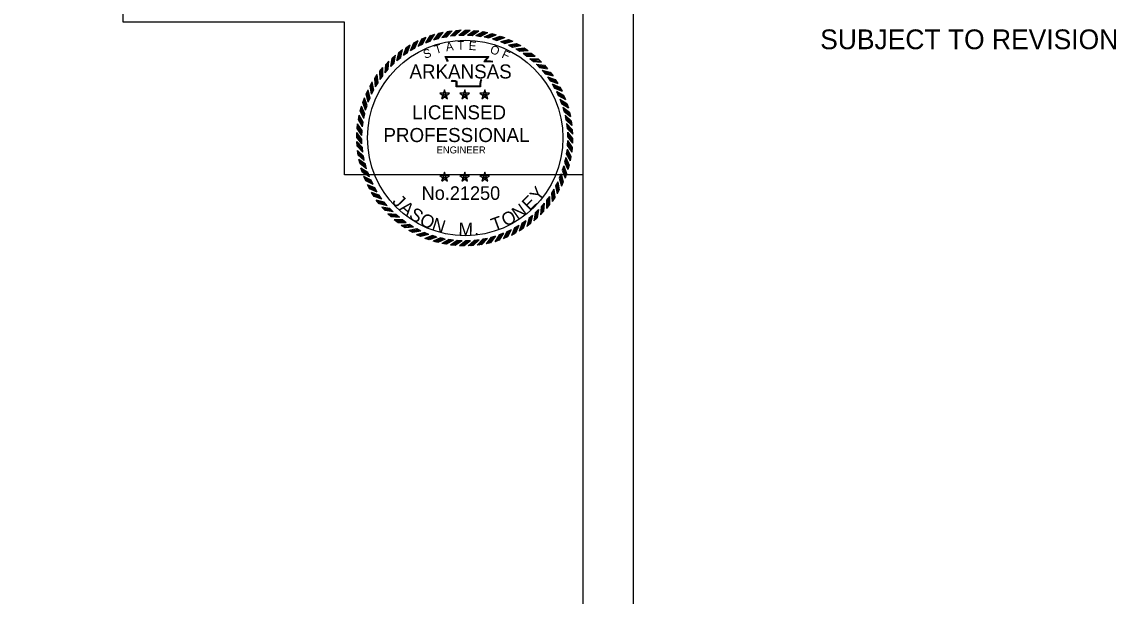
# Model space of a CAD drawing. Extents: x 0 to 1228740, y 0 to 152440.
# Drawn here: x 26.96 to 39.56, y 12.84 to 19.44 of the extents above; entities that cross this region are included whole.
import ezdxf

# ---------------------------------------------------------------- set-up
doc = ezdxf.new("R2010")
doc.units = 0
for name, color, linetype in [('G-ANNO-NPLT', 7, 'Continuous'), ('R_Border', 7, 'Continuous'), ('R_Draft', 7, 'Continuous'), ('R_No Plot', 7, 'Continuous'), ('STAMP', 7, 'Continuous')]:
    doc.layers.add(name, color=color, linetype=linetype)

msp = doc.modelspace()

# ---------------------------------------------------------------- linework, layer by layer
at = {"layer": 'G-ANNO-NPLT'}
msp.add_circle((32.064, 18.109), 1.124, dxfattribs=at)
at = {"layer": 'R_Border'}
msp.add_line((33.423, 0.577), (33.423, 21.423), dxfattribs=at)
msp.add_lwpolyline([(34, 22), (0, 22), (0, 0), (34, 0)], close=True, dxfattribs=at)
at = {"layer": 'R_No Plot'}
for points in [[(27.159, 21.423), (1.516, 21.423), (1.516, 0.577), (33.423, 0.577), (33.423, 17.685), (30.673, 17.685), (30.673, 19.442), (28.127, 19.442), (28.127, 20.435), (27.159, 20.435)], [(27.159, 21.423), (1.516, 21.423), (1.516, 10.871), (33.423, 10.871), (33.423, 17.685), (30.673, 17.685), (30.673, 19.442), (28.127, 19.442), (28.127, 20.435), (27.159, 20.435)]]:
    msp.add_lwpolyline(points, close=True, dxfattribs=at)
at = {"layer": 'STAMP'}
for p, q in [((31.566, 19.248), (31.615, 19.27)), ((31.661, 19.285), (31.713, 19.303)), ((31.76, 19.313), (31.812, 19.327)), ((31.797, 19.264), (31.851, 19.273)), ((31.86, 19.334), (31.914, 19.343)), ((31.894, 19.282), (31.948, 19.287)), ((31.962, 19.346), (32.016, 19.351)), ((31.991, 19.291), (32.045, 19.291)), ((32.065, 19.349), (32.12, 19.349)), ((32.089, 19.293), (32.143, 19.289)), ((32.167, 19.345), (32.221, 19.341)), ((32.186, 19.286), (32.24, 19.278)), ((32.269, 19.332), (32.323, 19.323)), ((32.283, 19.272), (32.336, 19.259)), ((32.369, 19.31), (32.422, 19.297)), ((32.467, 19.28), (32.519, 19.263)), ((31.385, 19.151), (31.43, 19.181)), ((31.473, 19.203), (31.521, 19.23)), ((31.522, 19.165), (31.571, 19.187)), ((31.611, 19.205), (31.662, 19.223)), ((31.703, 19.238), (31.755, 19.252)), ((32.378, 19.249), (32.43, 19.232)), ((32.472, 19.219), (32.522, 19.197)), ((32.562, 19.181), (32.61, 19.155)), ((32.563, 19.243), (32.613, 19.221)), ((32.654, 19.197), (32.703, 19.172)), ((32.742, 19.144), (32.788, 19.115)), ((31.223, 19.026), (31.262, 19.063)), ((31.279, 19), (31.322, 19.034)), ((31.301, 19.092), (31.344, 19.126)), ((31.355, 19.062), (31.401, 19.092)), ((31.436, 19.117), (31.484, 19.143)), ((32.649, 19.135), (32.694, 19.106)), ((32.731, 19.083), (32.775, 19.05)), ((32.809, 19.024), (32.85, 18.988)), ((32.825, 19.084), (32.869, 19.051)), ((32.903, 19.018), (32.944, 18.981)), ((31.083, 18.876), (31.116, 18.919)), ((31.143, 18.86), (31.179, 18.9)), ((31.15, 18.954), (31.186, 18.994)), ((31.208, 18.933), (31.248, 18.97)), ((32.883, 18.959), (32.92, 18.919)), ((32.976, 18.945), (33.013, 18.905)), ((31.023, 18.793), (31.052, 18.839)), ((31.084, 18.782), (31.117, 18.825)), ((32.95, 18.888), (32.984, 18.845)), ((33.011, 18.812), (33.041, 18.767)), ((33.041, 18.866), (33.075, 18.823)), ((33.101, 18.782), (33.131, 18.737)), ((30.924, 18.613), (30.946, 18.663)), ((30.97, 18.705), (30.995, 18.753)), ((30.986, 18.612), (31.012, 18.661)), ((31.032, 18.699), (31.061, 18.745)), ((31.827, 18.663), (31.793, 18.558)), ((31.861, 18.558), (31.827, 18.663)), ((32.058, 18.663), (32.024, 18.558)), ((32.092, 18.558), (32.058, 18.663)), ((32.289, 18.663), (32.255, 18.558)), ((32.323, 18.558), (32.289, 18.663)), ((33.066, 18.731), (33.092, 18.683)), ((33.114, 18.645), (33.136, 18.596)), ((33.153, 18.694), (33.179, 18.646)), ((30.887, 18.518), (30.904, 18.569)), ((30.949, 18.522), (30.97, 18.572)), ((31.882, 18.623), (31.772, 18.623)), ((31.773, 18.623), (31.861, 18.558)), ((31.794, 18.558), (31.882, 18.623)), ((31.82, 18.605), (31.836, 18.605)), ((31.828, 18.611), (31.828, 18.597)), ((32.113, 18.623), (32.003, 18.623)), ((32.003, 18.623), (32.092, 18.558)), ((32.024, 18.558), (32.113, 18.623)), ((32.05, 18.605), (32.067, 18.605)), ((32.058, 18.611), (32.058, 18.597)), ((32.344, 18.623), (32.234, 18.623)), ((32.234, 18.623), (32.323, 18.558)), ((32.255, 18.558), (32.344, 18.623)), ((32.281, 18.605), (32.297, 18.605)), ((32.289, 18.611), (32.289, 18.597)), ((33.155, 18.556), (33.173, 18.505)), ((33.197, 18.602), (33.22, 18.552)), ((30.857, 18.42), (30.87, 18.472)), ((30.918, 18.429), (30.935, 18.481)), ((33.188, 18.464), (33.202, 18.412)), ((33.234, 18.506), (33.252, 18.454)), ((33.263, 18.407), (33.277, 18.355)), ((30.822, 18.218), (30.826, 18.272)), ((30.835, 18.319), (30.844, 18.373)), ((30.881, 18.237), (30.89, 18.291)), ((30.896, 18.334), (30.909, 18.387)), ((33.213, 18.37), (33.223, 18.316)), ((33.231, 18.274), (33.236, 18.219)), ((33.283, 18.307), (33.293, 18.253)), ((30.817, 18.115), (30.817, 18.17)), ((30.874, 18.139), (30.878, 18.194)), ((33.241, 18.176), (33.241, 18.122)), ((33.295, 18.205), (33.3, 18.151)), ((30.821, 18.013), (30.816, 18.067)), ((30.876, 18.041), (30.876, 18.096)), ((33.242, 18.078), (33.238, 18.024)), ((33.299, 18.103), (33.3, 18.048)), ((30.833, 17.911), (30.824, 17.964)), ((30.886, 17.944), (30.881, 17.998)), ((30.903, 17.848), (30.894, 17.902)), ((33.236, 17.981), (33.227, 17.927)), ((33.281, 17.898), (33.273, 17.845)), ((33.294, 18), (33.29, 17.946)), ((30.854, 17.81), (30.84, 17.863)), ((30.883, 17.712), (30.864, 17.763)), ((30.929, 17.753), (30.915, 17.806)), ((33.198, 17.789), (33.181, 17.737)), ((33.221, 17.884), (33.208, 17.831)), ((33.26, 17.798), (33.247, 17.745)), ((30.919, 17.616), (30.897, 17.666)), ((30.962, 17.661), (30.944, 17.713)), ((31.882, 17.676), (31.772, 17.677)), ((31.773, 17.676), (31.861, 17.612)), ((31.827, 17.716), (31.793, 17.612)), ((31.794, 17.612), (31.882, 17.676)), ((31.82, 17.659), (31.836, 17.659)), ((31.861, 17.612), (31.827, 17.716)), ((31.828, 17.665), (31.828, 17.651)), ((32.113, 17.676), (32.003, 17.677)), ((32.003, 17.676), (32.092, 17.612)), ((32.058, 17.716), (32.024, 17.612)), ((32.024, 17.612), (32.113, 17.676)), ((32.05, 17.659), (32.067, 17.659)), ((32.092, 17.612), (32.058, 17.716)), ((32.058, 17.665), (32.058, 17.651)), ((32.344, 17.676), (32.234, 17.677)), ((32.234, 17.676), (32.323, 17.612)), ((32.289, 17.716), (32.255, 17.612)), ((32.255, 17.612), (32.344, 17.676)), ((32.281, 17.659), (32.297, 17.659)), ((32.323, 17.612), (32.289, 17.716)), ((32.289, 17.665), (32.289, 17.651)), ((33.168, 17.696), (33.147, 17.646)), ((33.23, 17.7), (33.213, 17.648)), ((30.964, 17.524), (30.938, 17.571)), ((31.003, 17.572), (30.98, 17.622)), ((31.051, 17.487), (31.024, 17.535)), ((33.085, 17.519), (33.056, 17.473)), ((33.13, 17.605), (33.105, 17.557)), ((33.147, 17.513), (33.121, 17.465)), ((33.192, 17.605), (33.171, 17.555)), ((31.016, 17.435), (30.986, 17.481)), ((31.075, 17.352), (31.041, 17.394)), ((31.105, 17.406), (31.075, 17.451)), ((33.033, 17.436), (33, 17.393)), ((33.094, 17.425), (33.064, 17.379)), ((31.141, 17.273), (31.104, 17.313)), ((31.167, 17.33), (31.133, 17.372)), ((31.234, 17.259), (31.197, 17.298)), ((32.909, 17.285), (32.869, 17.247)), ((32.967, 17.264), (32.93, 17.223)), ((32.974, 17.358), (32.937, 17.317)), ((33.034, 17.342), (33.001, 17.298)), ((31.213, 17.2), (31.173, 17.237)), ((31.291, 17.134), (31.248, 17.167)), ((31.307, 17.193), (31.267, 17.23)), ((31.385, 17.134), (31.342, 17.168)), ((32.761, 17.156), (32.716, 17.126)), ((32.838, 17.217), (32.795, 17.183)), ((32.894, 17.192), (32.854, 17.154)), ((31.374, 17.074), (31.328, 17.103)), ((31.462, 17.021), (31.414, 17.046)), ((31.468, 17.082), (31.422, 17.112)), ((31.555, 17.037), (31.507, 17.063)), ((31.645, 16.999), (31.595, 17.021)), ((32.506, 17.013), (32.455, 16.994)), ((32.595, 17.053), (32.545, 17.031)), ((32.643, 17.015), (32.596, 16.988)), ((32.68, 17.101), (32.633, 17.075)), ((32.732, 17.067), (32.686, 17.036)), ((32.815, 17.126), (32.773, 17.092)), ((31.554, 16.975), (31.504, 16.996)), ((31.649, 16.937), (31.598, 16.954)), ((31.738, 16.969), (31.686, 16.986)), ((31.748, 16.908), (31.695, 16.92)), ((31.833, 16.946), (31.78, 16.959)), ((31.848, 16.886), (31.794, 16.894)), ((31.93, 16.932), (31.876, 16.94)), ((31.95, 16.873), (31.895, 16.877)), ((32.028, 16.925), (31.973, 16.929)), ((32.126, 16.927), (32.071, 16.926)), ((32.223, 16.936), (32.169, 16.931)), ((32.256, 16.884), (32.203, 16.874)), ((32.319, 16.954), (32.266, 16.944)), ((32.357, 16.904), (32.304, 16.891)), ((32.414, 16.979), (32.361, 16.965)), ((32.455, 16.933), (32.404, 16.915)), ((32.551, 16.97), (32.501, 16.948)), ((32.052, 16.868), (31.998, 16.867)), ((32.154, 16.872), (32.1, 16.867))]:
    msp.add_line(p, q, dxfattribs=at)
for points in [[(31.571, 19.187), (31.615, 19.27)], [(31.611, 19.205), (31.661, 19.284)], [(31.627, 19.211), (31.678, 19.29)], [(31.645, 19.218), (31.696, 19.297)], [(31.662, 19.223), (31.713, 19.303)], [(31.703, 19.238), (31.76, 19.313)], [(31.72, 19.243), (31.777, 19.318)], [(31.738, 19.248), (31.795, 19.323)], [(31.755, 19.252), (31.812, 19.327)], [(31.797, 19.264), (31.86, 19.334)], [(31.814, 19.267), (31.878, 19.337)], [(31.833, 19.27), (31.896, 19.34)], [(31.851, 19.273), (31.914, 19.343)], [(31.893, 19.281), (31.962, 19.346)], [(31.911, 19.283), (31.98, 19.347)], [(31.93, 19.285), (31.998, 19.35)], [(31.948, 19.287), (32.016, 19.351)], [(31.991, 19.291), (32.065, 19.349)], [(32.008, 19.291), (32.083, 19.349)], [(32.027, 19.291), (32.102, 19.349)], [(32.045, 19.291), (32.12, 19.349)], [(32.089, 19.293), (32.167, 19.345)], [(32.106, 19.291), (32.184, 19.343)], [(32.125, 19.29), (32.203, 19.343)], [(32.143, 19.289), (32.221, 19.341)], [(32.186, 19.286), (32.269, 19.332)], [(32.204, 19.283), (32.286, 19.329)], [(32.222, 19.281), (32.305, 19.326)], [(32.24, 19.278), (32.323, 19.323)], [(32.283, 19.271), (32.369, 19.31)], [(32.3, 19.267), (32.386, 19.306)], [(32.319, 19.263), (32.404, 19.302)], [(32.336, 19.259), (32.422, 19.297)], [(32.378, 19.249), (32.467, 19.28)], [(32.395, 19.243), (32.484, 19.275)], [(31.355, 19.062), (31.385, 19.151)], [(31.37, 19.071), (31.4, 19.161)], [(31.385, 19.082), (31.415, 19.171)], [(31.401, 19.092), (31.43, 19.181)], [(31.436, 19.117), (31.473, 19.203)], [(31.452, 19.125), (31.489, 19.211)], [(31.468, 19.134), (31.505, 19.221)], [(31.484, 19.143), (31.521, 19.23)], [(31.522, 19.164), (31.566, 19.248)], [(31.538, 19.171), (31.582, 19.255)], [(31.555, 19.18), (31.599, 19.263)], [(32.413, 19.238), (32.502, 19.269)], [(32.43, 19.232), (32.519, 19.263)], [(32.471, 19.219), (32.562, 19.243)], [(32.487, 19.212), (32.579, 19.236)], [(32.505, 19.205), (32.596, 19.229)], [(32.522, 19.197), (32.613, 19.221)], [(32.562, 19.181), (32.654, 19.197)], [(32.577, 19.172), (32.67, 19.189)], [(32.594, 19.164), (32.687, 19.18)], [(32.61, 19.155), (32.703, 19.172)], [(32.648, 19.135), (32.742, 19.144)], [(31.208, 18.933), (31.223, 19.026)], [(31.221, 18.945), (31.235, 19.038)], [(31.234, 18.958), (31.249, 19.051)], [(31.248, 18.97), (31.262, 19.063)], [(31.279, 19), (31.301, 19.092)], [(31.293, 19.011), (31.315, 19.103)], [(31.307, 19.023), (31.329, 19.115)], [(31.322, 19.034), (31.344, 19.126)], [(31.862, 18.985), (31.833, 19.048), (32.335, 19.048), (32.293, 18.995), (32.327, 18.996), (32.356, 18.996), (32.384, 18.993)], [(31.87, 18.988), (31.846, 19.04), (32.319, 19.04), (32.277, 18.987), (32.328, 18.988), (32.356, 18.988), (32.383, 18.985)], [(32.663, 19.126), (32.757, 19.135)], [(32.679, 19.116), (32.773, 19.125)], [(32.694, 19.106), (32.788, 19.115)], [(32.731, 19.083), (32.825, 19.084)], [(32.745, 19.072), (32.839, 19.073)], [(32.76, 19.061), (32.854, 19.062)], [(32.775, 19.05), (32.869, 19.051)], [(32.809, 19.024), (32.903, 19.018)], [(31.106, 18.811), (31.105, 18.905)], [(31.117, 18.825), (31.116, 18.919)], [(31.143, 18.86), (31.15, 18.954)], [(31.155, 18.873), (31.162, 18.967)], [(31.167, 18.887), (31.174, 18.981)], [(31.179, 18.9), (31.186, 18.994)], [(32.822, 19.012), (32.916, 19.006)], [(32.837, 19), (32.93, 18.993)], [(32.85, 18.988), (32.944, 18.981)], [(32.882, 18.959), (32.975, 18.945)], [(32.894, 18.946), (32.987, 18.932)], [(32.908, 18.933), (33.001, 18.918)], [(32.92, 18.919), (33.013, 18.905)], [(31.032, 18.699), (31.023, 18.793)], [(31.041, 18.714), (31.033, 18.807)], [(31.051, 18.73), (31.042, 18.824)], [(31.061, 18.745), (31.052, 18.839)], [(31.084, 18.782), (31.083, 18.876)], [(31.095, 18.796), (31.094, 18.89)], [(32.256, 18.775), (32.248, 18.768), (32.245, 18.757), (32.242, 18.731), (32.242, 18.697), (31.962, 18.697), (31.962, 18.743), (31.962, 18.754), (31.95, 18.757), (31.911, 18.757), (31.904, 18.768)], [(32.251, 18.781), (32.241, 18.772), (32.237, 18.759), (32.234, 18.732), (32.234, 18.705), (31.97, 18.705), (31.97, 18.743), (31.97, 18.76), (31.952, 18.765), (31.915, 18.765), (31.91, 18.772)], [(32.95, 18.888), (33.041, 18.866)], [(32.961, 18.874), (33.052, 18.852)], [(32.973, 18.86), (33.064, 18.838)], [(32.984, 18.846), (33.075, 18.823)], [(33.011, 18.812), (33.101, 18.782)], [(33.021, 18.797), (33.11, 18.768)], [(33.032, 18.782), (33.121, 18.752)], [(33.041, 18.767), (33.131, 18.737)], [(30.963, 18.556), (30.939, 18.647)], [(30.97, 18.572), (30.946, 18.663)], [(30.986, 18.612), (30.97, 18.705)], [(30.995, 18.628), (30.978, 18.72)], [(31.003, 18.645), (30.987, 18.737)], [(31.012, 18.66), (30.995, 18.753)], [(33.066, 18.731), (33.153, 18.694)], [(33.074, 18.715), (33.161, 18.679)], [(33.084, 18.699), (33.17, 18.662)], [(33.092, 18.683), (33.179, 18.646)], [(33.114, 18.646), (33.197, 18.602)], [(30.918, 18.429), (30.887, 18.518)], [(30.924, 18.446), (30.892, 18.534)], [(30.929, 18.464), (30.898, 18.552)], [(30.935, 18.481), (30.904, 18.569)], [(30.949, 18.522), (30.925, 18.613)], [(30.956, 18.538), (30.932, 18.629)], [(33.121, 18.629), (33.204, 18.586)], [(33.129, 18.612), (33.212, 18.568)], [(33.136, 18.596), (33.22, 18.552)], [(33.155, 18.557), (33.234, 18.506)], [(33.16, 18.54), (33.24, 18.489)], [(33.167, 18.522), (33.246, 18.472)], [(30.896, 18.334), (30.857, 18.42)], [(30.9, 18.351), (30.861, 18.437)], [(30.904, 18.369), (30.865, 18.455)], [(30.908, 18.387), (30.87, 18.473)], [(33.173, 18.505), (33.252, 18.454)], [(33.188, 18.464), (33.263, 18.407)], [(33.192, 18.447), (33.267, 18.39)], [(33.197, 18.429), (33.272, 18.372)], [(33.202, 18.412), (33.277, 18.355)], [(30.878, 18.194), (30.826, 18.272)], [(30.881, 18.237), (30.835, 18.319)], [(30.884, 18.254), (30.838, 18.337)], [(30.886, 18.273), (30.841, 18.355)], [(30.889, 18.291), (30.844, 18.373)], [(33.213, 18.37), (33.283, 18.307)], [(33.216, 18.353), (33.286, 18.29)], [(33.22, 18.334), (33.29, 18.271)], [(33.223, 18.316), (33.293, 18.253)], [(33.231, 18.274), (33.295, 18.205)], [(30.875, 18.096), (30.817, 18.17)], [(30.875, 18.078), (30.817, 18.152)], [(30.875, 18.139), (30.822, 18.218)], [(30.876, 18.157), (30.824, 18.235)], [(30.877, 18.176), (30.825, 18.254)], [(33.232, 18.256), (33.297, 18.188)], [(33.235, 18.237), (33.299, 18.169)], [(33.236, 18.219), (33.301, 18.151)], [(33.241, 18.176), (33.299, 18.103)], [(33.241, 18.159), (33.299, 18.085)], [(33.241, 18.14), (33.3, 18.066)], [(30.881, 17.998), (30.816, 18.067)], [(30.876, 18.059), (30.817, 18.133)], [(30.876, 18.041), (30.817, 18.115)], [(30.882, 17.98), (30.818, 18.049)], [(30.884, 17.961), (30.82, 18.03)], [(30.886, 17.944), (30.821, 18.013)], [(33.238, 18.024), (33.29, 17.946)], [(33.24, 18.042), (33.292, 17.964)], [(33.241, 18.122), (33.3, 18.048)], [(33.241, 18.061), (33.293, 17.983)], [(33.242, 18.078), (33.294, 18)], [(30.894, 17.901), (30.824, 17.964)], [(30.897, 17.884), (30.827, 17.947)], [(30.9, 17.865), (30.83, 17.928)], [(30.903, 17.848), (30.833, 17.911)], [(33.221, 17.884), (33.26, 17.798)], [(33.227, 17.927), (33.273, 17.845)], [(33.23, 17.945), (33.276, 17.862)], [(33.233, 17.964), (33.278, 17.881)], [(33.236, 17.981), (33.281, 17.898)], [(30.915, 17.806), (30.84, 17.863)], [(30.919, 17.788), (30.844, 17.845)], [(30.924, 17.77), (30.85, 17.827)], [(30.929, 17.753), (30.854, 17.81)], [(30.944, 17.713), (30.864, 17.763)], [(33.193, 17.772), (33.224, 17.683)], [(33.198, 17.789), (33.23, 17.7)], [(33.208, 17.831), (33.247, 17.745)], [(33.213, 17.849), (33.251, 17.763)], [(33.217, 17.867), (33.255, 17.781)], [(30.95, 17.695), (30.87, 17.746)], [(30.956, 17.678), (30.877, 17.728)], [(30.962, 17.661), (30.883, 17.712)], [(30.98, 17.622), (30.897, 17.666)], [(30.988, 17.605), (30.904, 17.649)], [(30.996, 17.588), (30.912, 17.632)], [(33.147, 17.646), (33.171, 17.555)], [(33.154, 17.662), (33.178, 17.571)], [(33.161, 17.68), (33.185, 17.589)], [(33.168, 17.696), (33.192, 17.605)], [(33.181, 17.737), (33.213, 17.648)], [(33.187, 17.754), (33.219, 17.665)], [(31.003, 17.572), (30.919, 17.616)], [(31.024, 17.535), (30.938, 17.571)], [(31.033, 17.519), (30.946, 17.556)], [(31.042, 17.502), (30.956, 17.539)], [(31.051, 17.487), (30.964, 17.524)], [(33.085, 17.519), (33.094, 17.425)], [(33.105, 17.557), (33.121, 17.465)], [(33.113, 17.573), (33.13, 17.48)], [(33.122, 17.59), (33.138, 17.497)], [(33.13, 17.605), (33.147, 17.513)], [(31.075, 17.451), (30.986, 17.481)], [(31.085, 17.436), (30.996, 17.466)], [(31.096, 17.42), (31.007, 17.45)], [(31.105, 17.406), (31.016, 17.435)], [(31.133, 17.372), (31.041, 17.394)], [(33, 17.393), (33.001, 17.298)], [(33.011, 17.407), (33.012, 17.313)], [(33.022, 17.422), (33.023, 17.328)], [(33.033, 17.436), (33.034, 17.342)], [(33.056, 17.473), (33.064, 17.379)], [(33.066, 17.488), (33.074, 17.394)], [(33.075, 17.504), (33.084, 17.41)], [(31.144, 17.358), (31.052, 17.38)], [(31.156, 17.343), (31.065, 17.365)], [(31.167, 17.329), (31.075, 17.352)], [(31.197, 17.298), (31.104, 17.313)], [(31.209, 17.285), (31.116, 17.299)], [(31.222, 17.271), (31.129, 17.286)], [(31.234, 17.259), (31.141, 17.273)], [(32.882, 17.26), (32.868, 17.167)], [(32.896, 17.273), (32.881, 17.18)], [(32.909, 17.285), (32.894, 17.192)], [(32.937, 17.317), (32.93, 17.223)], [(32.95, 17.331), (32.943, 17.237)], [(32.962, 17.345), (32.955, 17.251)], [(32.974, 17.358), (32.967, 17.264)], [(31.267, 17.23), (31.173, 17.237)], [(31.28, 17.218), (31.186, 17.224)], [(31.294, 17.205), (31.2, 17.212)], [(31.307, 17.193), (31.213, 17.2)], [(31.342, 17.168), (31.248, 17.167)], [(31.356, 17.156), (31.262, 17.155)], [(31.372, 17.145), (31.277, 17.144)], [(31.385, 17.134), (31.291, 17.134)], [(32.731, 17.136), (32.702, 17.046)], [(32.747, 17.146), (32.717, 17.057)], [(32.761, 17.156), (32.732, 17.067)], [(32.795, 17.183), (32.773, 17.092)], [(32.809, 17.194), (32.787, 17.103)], [(32.824, 17.207), (32.802, 17.115)], [(32.838, 17.217), (32.816, 17.126)], [(32.869, 17.247), (32.854, 17.154)], [(31.422, 17.112), (31.328, 17.103)], [(31.437, 17.102), (31.344, 17.093)], [(31.453, 17.092), (31.36, 17.083)], [(31.468, 17.082), (31.374, 17.074)], [(31.507, 17.062), (31.414, 17.046)], [(31.523, 17.054), (31.43, 17.037)], [(31.54, 17.045), (31.447, 17.029)], [(31.555, 17.037), (31.462, 17.021)], [(31.595, 17.02), (31.504, 16.996)], [(31.612, 17.013), (31.521, 16.989)], [(31.629, 17.006), (31.538, 16.982)], [(32.489, 17.007), (32.439, 16.928)], [(32.506, 17.013), (32.455, 16.933)], [(32.545, 17.031), (32.501, 16.948)], [(32.562, 17.038), (32.518, 16.955)], [(32.579, 17.046), (32.535, 16.963)], [(32.595, 17.053), (32.551, 16.97)], [(32.633, 17.075), (32.596, 16.988)], [(32.649, 17.083), (32.612, 16.997)], [(32.665, 17.093), (32.628, 17.006)], [(32.68, 17.101), (32.643, 17.015)], [(32.716, 17.126), (32.686, 17.036)], [(31.645, 16.999), (31.554, 16.975)], [(31.686, 16.986), (31.598, 16.954)], [(31.704, 16.98), (31.615, 16.949)], [(31.722, 16.974), (31.633, 16.943)], [(31.738, 16.969), (31.649, 16.937)], [(31.78, 16.959), (31.695, 16.92)], [(31.798, 16.955), (31.712, 16.916)], [(31.816, 16.951), (31.731, 16.912)], [(31.833, 16.946), (31.748, 16.908)], [(31.876, 16.94), (31.794, 16.894)], [(31.894, 16.937), (31.812, 16.891)], [(31.913, 16.935), (31.831, 16.889)], [(31.93, 16.932), (31.848, 16.886)], [(31.973, 16.929), (31.895, 16.877)], [(31.992, 16.927), (31.913, 16.875)], [(32.01, 16.927), (31.932, 16.874)], [(32.028, 16.925), (31.95, 16.873)], [(32.071, 16.926), (31.998, 16.867)], [(32.089, 16.926), (32.016, 16.867)], [(32.108, 16.927), (32.035, 16.868)], [(32.126, 16.927), (32.052, 16.868)], [(32.169, 16.931), (32.1, 16.867)], [(32.187, 16.933), (32.118, 16.868)], [(32.206, 16.935), (32.137, 16.87)], [(32.223, 16.936), (32.155, 16.872)], [(32.266, 16.944), (32.203, 16.874)], [(32.284, 16.947), (32.221, 16.877)], [(32.302, 16.951), (32.239, 16.881)], [(32.319, 16.954), (32.256, 16.884)], [(32.361, 16.965), (32.304, 16.891)], [(32.379, 16.97), (32.322, 16.895)], [(32.397, 16.975), (32.34, 16.9)], [(32.414, 16.979), (32.357, 16.904)], [(32.455, 16.994), (32.404, 16.915)], [(32.472, 17), (32.421, 16.921)]]:
    msp.add_lwpolyline(points, dxfattribs=at)

# ---------------------------------------------------------------- texts
at = {"layer": 'R_Draft'}
msp.add_text('SUBJECT TO REVISION', height=0.22743, rotation=0, dxfattribs=at).set_placement((36.15, 19.13))
at = {"layer": 'STAMP'}
for s, height, rotation, p in [('T', 0.099, 16.9015, (31.727, 19.074)), ('A', 0.099, 8.6788, (31.847, 19.106)), ('T', 0.099, 1.4789, (31.975, 19.125)), ('E', 0.099, 356.672, (32.102, 19.122)), ('O', 0.099, 341.2218, (32.342, 19.088)), ('S', 0.099, 19.7726, (31.601, 19.018)), ('F', 0.099, 335.3628, (32.475, 19.036)), ('Y', 0.15, 51.7852, (32.912, 17.368)), ('J', 0.15, 314.0187, (31.215, 17.369)), ('E', 0.15, 44.1244, (32.805, 17.262)), ('A', 0.15, 319.8555, (31.295, 17.286)), ('S', 0.15, 327.1515, (31.406, 17.195)), ('O', 0.15, 27.3436, (32.529, 17.084)), ('N', 0.15, 35.3692, (32.668, 17.159)), ('O', 0.15, 334.4475, (31.527, 17.119)), ('N', 0.15, 342.4731, (31.67, 17.054)), ('M', 0.15, 358.8891, (31.985, 16.986)), ('T', 0.15, 20.0476, (32.395, 17.033)), ('.', 0.15, 8.3739, (32.171, 16.988))]:
    msp.add_text(s, height=height, rotation=rotation, dxfattribs=at).set_placement(p)
for s, height, p in [('ARKANSAS', 0.1615, (31.423, 18.793)), ('LICENSED', 0.1615, (31.454, 18.323)), ('PROFESSIONAL', 0.16155, (31.123, 18.062)), ('ENGINEER', 0.0808, (31.735, 17.931)), ('No.21250', 0.1558, (31.563, 17.397))]:
    msp.add_text(s, height=height, dxfattribs=at).set_placement(p)

doc.saveas('drawing.dxf')
